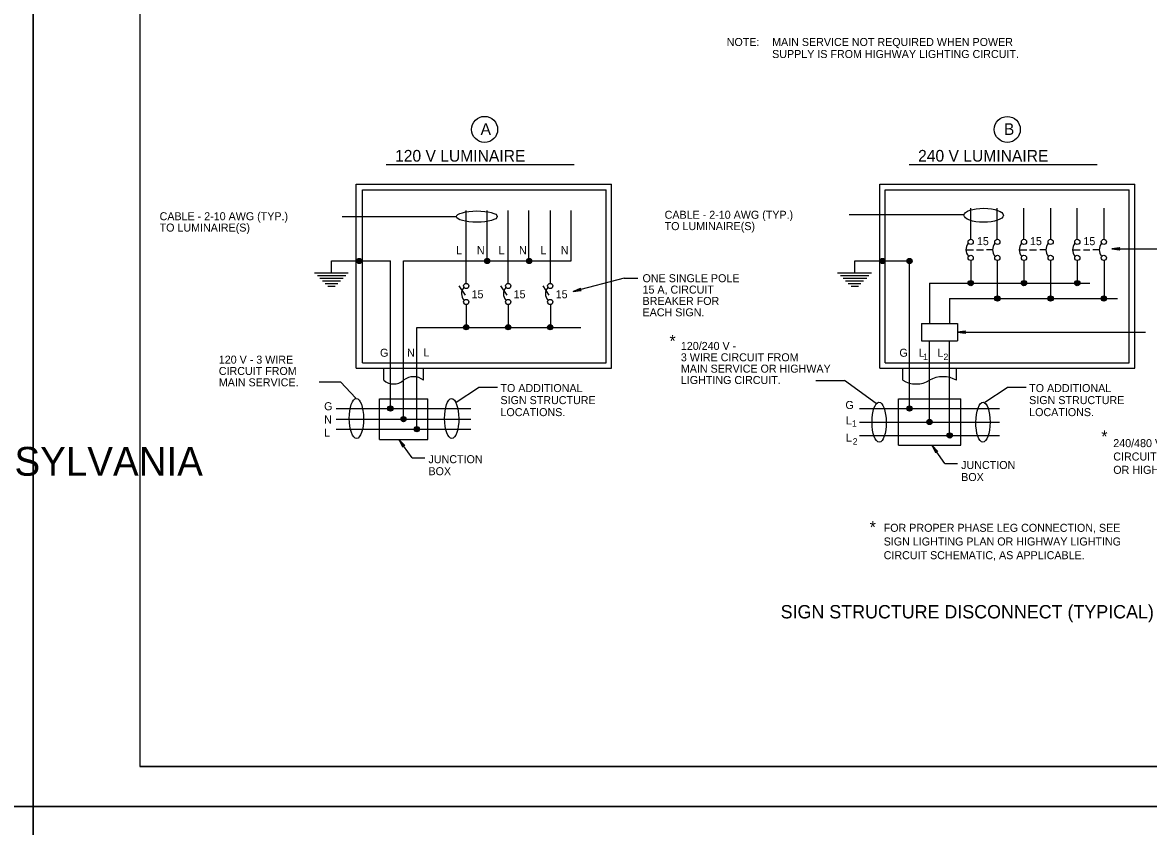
# Model space of a CAD drawing. Extents: x 36 to 2622, y -5330 to 219.
# Drawn here: x 872.9 to 1294.3, y -4743.3 to -4442.5 of the extents above; entities that cross this region are included whole.
import ezdxf

# ---------------------------------------------------------------- set-up
doc = ezdxf.new("R2010")
doc.units = 0
for name, color, linetype in [('1', 7, 'Continuous'), ('2', 7, 'Continuous'), ('3', 7, 'Continuous'), ('PLT-BNDY', 7, 'Continuous')]:
    doc.layers.add(name, color=color, linetype=linetype)

# ---------------------------------------------------------------- blocks, each defined once
blk = doc.blocks.new('RARROW')
at = {"layer": '3'}
blk.add_lwpolyline([(-2.2695, 0.285), (-2.184875, 0.12075), (0, 0), (-2.2695, 0.285), (-2.38575, 0.384625), (0, 0), (-2.183125, -0.108), (-2.262875, -0.2705), (0, 0), (-2.38575, -0.379125), (-2.262875, -0.2705)], dxfattribs=at)

msp = doc.modelspace()

# ---------------------------------------------------------------- linework, layer by layer
at = {"layer": '1'}
for p, q in [((916.86, -4156.83), (916.86, -4720.83)), ((1702.86, -4720.83), (916.86, -4720.83)), ((916.86, -4720.83), (1502.86, -4720.83))]:
    msp.add_line(p, q, dxfattribs=at)
at = {"layer": '2'}
for p, q in [((1008.98, -4495.7), (1079.36, -4495.7)), ((1204.73, -4495.7), (1275.11, -4495.7)), ((997.86, -4502.95), (1093.36, -4502.95)), ((997.86, -4571.83), (997.86, -4502.95)), ((1093.36, -4571.83), (1093.36, -4502.95)), ((1193.73, -4502.95), (1289.23, -4502.95)), ((1193.73, -4571.83), (1193.73, -4502.95)), ((1289.23, -4571.83), (1289.23, -4502.95)), ((1000.11, -4505.08), (1091.36, -4505.08)), ((1000.11, -4569.83), (1000.11, -4505.08)), ((1091.36, -4569.83), (1091.36, -4505.08)), ((1195.73, -4505.08), (1287.11, -4505.08)), ((1195.73, -4569.83), (1195.73, -4505.08)), ((1287.11, -4569.83), (1287.11, -4505.08)), ((1038.98, -4540.08), (1038.98, -4512.83)), ((1046.86, -4531.7), (1046.86, -4512.83)), ((1054.73, -4540.08), (1054.73, -4512.83)), ((1062.48, -4531.7), (1062.48, -4512.83)), ((1070.48, -4540.08), (1070.48, -4512.83)), ((1078.23, -4531.7), (1078.23, -4512.83)), ((1227.86, -4523.58), (1227.86, -4511.95)), ((1237.73, -4523.58), (1237.73, -4511.95)), ((1247.73, -4523.58), (1247.73, -4511.95)), ((1257.73, -4523.58), (1257.73, -4511.95)), ((1267.61, -4523.58), (1267.61, -4511.95)), ((1277.73, -4523.58), (1277.73, -4511.95)), ((1035.3, -4515.2), (992.51, -4515.2)), ((1182.36, -4514.33), (1225.36, -4514.33)), ((1225.98, -4527.58), (1228.86, -4527.58)), ((1229.98, -4527.58), (1232.61, -4527.58)), ((1235.98, -4527.58), (1233.73, -4527.58)), ((1245.98, -4527.58), (1248.86, -4527.58)), ((1249.86, -4527.58), (1252.48, -4527.58)), ((1255.86, -4527.58), (1253.61, -4527.58)), ((1265.86, -4527.58), (1268.73, -4527.58)), ((1269.98, -4527.58), (1272.36, -4527.58)), ((1275.98, -4527.58), (1273.48, -4527.58)), ((1280.61, -4527.2), (1299.36, -4527.2)), ((988.61, -4536.33), (988.61, -4531.7)), ((988.61, -4531.7), (1010.61, -4531.7)), ((1010.61, -4586.95), (1010.61, -4531.7)), ((1015.54, -4590.93), (1015.54, -4531.7)), ((1015.54, -4531.7), (1078.23, -4531.7)), ((1184.48, -4531.7), (1204.86, -4531.7)), ((1184.48, -4536.33), (1184.48, -4531.7)), ((1204.86, -4586.95), (1204.86, -4531.7)), ((1227.86, -4531.58), (1227.86, -4540.08)), ((1237.73, -4531.58), (1237.73, -4545.83)), ((1247.73, -4531.58), (1247.73, -4540.08)), ((1257.73, -4545.83), (1257.73, -4531.58)), ((1267.61, -4531.58), (1267.61, -4540.08)), ((1277.73, -4531.58), (1277.73, -4545.83)), ((994.86, -4536.33), (982.23, -4536.33)), ((993.98, -4537.33), (983.36, -4537.33)), ((992.98, -4538.33), (984.23, -4538.33)), ((1098.11, -4538.2), (1078.98, -4543.2)), ((1098.11, -4538.2), (1103.23, -4538.2)), ((1190.73, -4536.33), (1177.98, -4536.33)), ((1189.73, -4537.33), (1179.11, -4537.33)), ((1188.86, -4538.33), (1180.11, -4538.33)), ((991.98, -4539.33), (985.23, -4539.33)), ((990.98, -4540.33), (986.23, -4540.33)), ((989.98, -4541.33), (987.23, -4541.33)), ((1038.73, -4544.58), (1036.36, -4541.08)), ((1054.36, -4544.58), (1051.98, -4541.08)), ((1069.98, -4544.58), (1067.73, -4541.08)), ((1187.73, -4539.33), (1180.98, -4539.33)), ((1186.73, -4540.33), (1181.98, -4540.33)), ((1185.86, -4541.33), (1183.11, -4541.33)), ((1212.36, -4540.08), (1272.36, -4540.08)), ((1212.36, -4540.08), (1212.36, -4555.08)), ((1219.86, -4545.83), (1282.73, -4545.83)), ((1219.86, -4545.83), (1219.86, -4555.08)), ((1038.98, -4548.08), (1038.98, -4556.58)), ((1054.73, -4548.08), (1054.73, -4556.58)), ((1070.48, -4548.08), (1070.48, -4556.58)), ((1209.36, -4555.08), (1222.86, -4555.08)), ((1209.36, -4555.08), (1209.36, -4561.58)), ((1222.86, -4555.08), (1222.86, -4561.58)), ((1020.48, -4594.68), (1020.48, -4556.58)), ((1020.48, -4556.58), (1081.86, -4556.58)), ((1222.86, -4558.33), (1293.23, -4558.33)), ((1209.36, -4561.58), (1222.86, -4561.58)), ((1212.36, -4592.08), (1212.36, -4561.58)), ((1219.86, -4597.08), (1219.86, -4561.58)), ((997.86, -4571.83), (1093.36, -4571.83)), ((1000.11, -4569.83), (1091.36, -4569.83)), ((1008.11, -4576.33), (1008.11, -4571.83)), ((1022.98, -4576.33), (1022.98, -4571.83)), ((1193.73, -4571.83), (1289.23, -4571.83)), ((1195.73, -4569.83), (1287.11, -4569.83)), ((1202.36, -4576.33), (1202.36, -4571.83)), ((1222.48, -4576.33), (1222.48, -4571.83)), ((983.91, -4576.91), (991.91, -4576.91)), ((991.91, -4576.91), (997.73, -4583.12)), ((1035.18, -4584.58), (1043.53, -4579.12)), ((1050.68, -4579.12), (1043.53, -4579.12)), ((1169.82, -4576.48), (1180.59, -4576.48)), ((1192.39, -4585.13), (1180.59, -4576.48)), ((1233.05, -4584.58), (1241.41, -4579.12)), ((1248.55, -4579.12), (1241.41, -4579.12)), ((1006.48, -4598.53), (1006.48, -4583.33)), ((1006.48, -4583.33), (1024.61, -4583.33)), ((1024.61, -4598.53), (1024.61, -4583.33)), ((1200.73, -4583.33), (1224.11, -4583.33)), ((1200.73, -4600.7), (1200.73, -4583.33)), ((1224.11, -4600.7), (1224.11, -4583.33)), ((990.36, -4586.95), (1040.73, -4586.95)), ((1186.23, -4586.95), (1238.61, -4586.95)), ((990.36, -4590.93), (1040.73, -4590.93)), ((1186.23, -4592.08), (1238.61, -4592.08)), ((990.36, -4594.68), (1040.73, -4594.68)), ((1186.23, -4597.08), (1238.61, -4597.08)), ((1006.48, -4598.53), (1024.61, -4598.53)), ((1018.73, -4605.41), (1013.86, -4598.66)), ((1200.73, -4600.7), (1224.11, -4600.7)), ((1218.11, -4607.58), (1213.36, -4600.83)), ((1018.73, -4605.41), (1023.48, -4605.41)), ((1218.11, -4607.58), (1222.86, -4607.58))]:
    msp.add_line(p, q, dxfattribs=at)
for centre, radius in [((1045.87, -4482.52), 4.87), ((1241.49, -4482.54), 4.87), ((1227.8, -4524.6), 0.976), ((1237.77, -4524.59), 0.976), ((1247.74, -4524.6), 0.976), ((1257.71, -4524.59), 0.976), ((1267.69, -4524.6), 0.976), ((1277.65, -4524.59), 0.976), ((1227.8, -4530.59), 0.976), ((1237.77, -4530.59), 0.976), ((1247.74, -4530.59), 0.976), ((1257.71, -4530.59), 0.976), ((1267.69, -4530.59), 0.976), ((1277.65, -4530.59), 0.976), ((998.97, -4531.77), 0.976), ((998.97, -4531.77), 0.907), ((998.97, -4531.77), 0.838), ((998.97, -4531.77), 0.768), ((998.97, -4531.77), 0.699), ((998.97, -4531.77), 0.63), ((998.97, -4531.77), 0.56), ((998.97, -4531.77), 0.491), ((998.97, -4531.77), 0.422), ((998.97, -4531.77), 0.352), ((998.97, -4531.77), 0.283), ((998.97, -4531.77), 0.214), ((998.97, -4531.77), 0.144), ((998.97, -4531.77), 0.0749), ((1046.85, -4531.76), 0.976), ((1046.85, -4531.76), 0.907), ((1046.85, -4531.76), 0.838), ((1046.85, -4531.76), 0.768), ((1046.85, -4531.76), 0.699), ((1046.85, -4531.76), 0.63), ((1046.85, -4531.76), 0.56), ((1046.85, -4531.76), 0.491), ((1046.85, -4531.76), 0.422), ((1046.85, -4531.76), 0.352), ((1046.85, -4531.76), 0.283), ((1046.85, -4531.76), 0.214), ((1046.85, -4531.76), 0.144), ((1046.85, -4531.76), 0.0749), ((1062.56, -4531.76), 0.976), ((1062.56, -4531.76), 0.907), ((1062.56, -4531.76), 0.838), ((1062.56, -4531.76), 0.768), ((1062.56, -4531.76), 0.699), ((1062.56, -4531.76), 0.63), ((1062.56, -4531.76), 0.56), ((1062.56, -4531.76), 0.491), ((1062.56, -4531.76), 0.422), ((1062.56, -4531.76), 0.352), ((1062.56, -4531.76), 0.283), ((1062.56, -4531.76), 0.214), ((1062.56, -4531.76), 0.144), ((1062.56, -4531.76), 0.0749), ((1194.76, -4531.77), 0.976), ((1194.76, -4531.77), 0.907), ((1194.76, -4531.77), 0.838), ((1194.76, -4531.77), 0.768), ((1194.76, -4531.77), 0.699), ((1194.76, -4531.77), 0.63), ((1194.76, -4531.77), 0.56), ((1194.76, -4531.77), 0.491), ((1194.76, -4531.77), 0.422), ((1194.76, -4531.77), 0.352), ((1194.76, -4531.77), 0.283), ((1194.76, -4531.77), 0.214), ((1194.76, -4531.77), 0.144), ((1194.76, -4531.77), 0.0749), ((1204.87, -4531.76), 0.976), ((1204.87, -4531.76), 0.907), ((1204.87, -4531.76), 0.838), ((1204.87, -4531.76), 0.768), ((1204.87, -4531.76), 0.699), ((1204.87, -4531.76), 0.63), ((1204.87, -4531.76), 0.56), ((1204.87, -4531.76), 0.491), ((1204.87, -4531.76), 0.422), ((1204.87, -4531.76), 0.352), ((1204.87, -4531.76), 0.283), ((1204.87, -4531.76), 0.214), ((1204.87, -4531.76), 0.144), ((1204.87, -4531.76), 0.0749), ((1038.99, -4541.1), 0.976), ((1054.7, -4541.1), 0.976), ((1070.41, -4541.1), 0.976), ((1227.79, -4540.02), 0.976), ((1227.79, -4540.02), 0.907), ((1227.79, -4540.02), 0.838), ((1227.79, -4540.02), 0.768), ((1227.79, -4540.02), 0.699), ((1227.79, -4540.02), 0.63), ((1227.79, -4540.02), 0.56), ((1227.79, -4540.02), 0.491), ((1227.79, -4540.02), 0.422), ((1227.79, -4540.02), 0.352), ((1227.79, -4540.02), 0.283), ((1227.79, -4540.02), 0.214), ((1227.79, -4540.02), 0.144), ((1227.79, -4540.02), 0.0749), ((1247.74, -4540.02), 0.976), ((1247.74, -4540.02), 0.907), ((1247.74, -4540.02), 0.838), ((1247.74, -4540.02), 0.768), ((1247.74, -4540.02), 0.699), ((1247.74, -4540.02), 0.63), ((1247.74, -4540.02), 0.56), ((1247.74, -4540.02), 0.491), ((1247.74, -4540.02), 0.422), ((1247.74, -4540.02), 0.352), ((1247.74, -4540.02), 0.283), ((1247.74, -4540.02), 0.214), ((1247.74, -4540.02), 0.144), ((1247.74, -4540.02), 0.0749), ((1267.68, -4540.02), 0.976), ((1267.68, -4540.02), 0.907), ((1267.68, -4540.02), 0.838), ((1267.68, -4540.02), 0.768), ((1267.68, -4540.02), 0.699), ((1267.68, -4540.02), 0.63), ((1267.68, -4540.02), 0.56), ((1267.68, -4540.02), 0.491), ((1267.68, -4540.02), 0.422), ((1267.68, -4540.02), 0.352), ((1267.68, -4540.02), 0.283), ((1267.68, -4540.02), 0.214), ((1267.68, -4540.02), 0.144), ((1267.68, -4540.02), 0.0749), ((1038.99, -4547.09), 0.976), ((1054.7, -4547.09), 0.976), ((1070.41, -4547.09), 0.976), ((1237.77, -4545.79), 0.976), ((1237.77, -4545.79), 0.907), ((1237.77, -4545.79), 0.838), ((1237.77, -4545.79), 0.768), ((1237.77, -4545.79), 0.699), ((1237.77, -4545.79), 0.63), ((1237.77, -4545.79), 0.56), ((1237.77, -4545.79), 0.491), ((1237.77, -4545.79), 0.422), ((1237.77, -4545.79), 0.352), ((1237.77, -4545.79), 0.283), ((1237.77, -4545.79), 0.214), ((1237.77, -4545.79), 0.144), ((1237.77, -4545.79), 0.0749), ((1257.71, -4545.79), 0.976), ((1257.71, -4545.79), 0.907), ((1257.71, -4545.79), 0.838), ((1257.71, -4545.79), 0.768), ((1257.71, -4545.79), 0.699), ((1257.71, -4545.79), 0.63), ((1257.71, -4545.79), 0.56), ((1257.71, -4545.79), 0.491), ((1257.71, -4545.79), 0.422), ((1257.71, -4545.79), 0.352), ((1257.71, -4545.79), 0.283), ((1257.71, -4545.79), 0.214), ((1257.71, -4545.79), 0.144), ((1257.71, -4545.79), 0.0749), ((1277.65, -4545.79), 0.976), ((1277.65, -4545.79), 0.907), ((1277.65, -4545.79), 0.838), ((1277.65, -4545.79), 0.768), ((1277.65, -4545.79), 0.699), ((1277.65, -4545.79), 0.63), ((1277.65, -4545.79), 0.56), ((1277.65, -4545.79), 0.491), ((1277.65, -4545.79), 0.422), ((1277.65, -4545.79), 0.352), ((1277.65, -4545.79), 0.283), ((1277.65, -4545.79), 0.214), ((1277.65, -4545.79), 0.144), ((1277.65, -4545.79), 0.0749), ((1038.99, -4556.52), 0.976), ((1038.99, -4556.52), 0.907), ((1038.99, -4556.52), 0.838), ((1038.99, -4556.52), 0.768), ((1038.99, -4556.52), 0.699), ((1038.99, -4556.52), 0.63), ((1038.99, -4556.52), 0.56), ((1038.99, -4556.52), 0.491), ((1038.99, -4556.52), 0.422), ((1038.99, -4556.52), 0.352), ((1038.99, -4556.52), 0.283), ((1038.99, -4556.52), 0.214), ((1038.99, -4556.52), 0.144), ((1038.99, -4556.52), 0.0749), ((1054.7, -4556.52), 0.976), ((1054.7, -4556.52), 0.907), ((1054.7, -4556.52), 0.838), ((1054.7, -4556.52), 0.768), ((1054.7, -4556.52), 0.699), ((1054.7, -4556.52), 0.63), ((1054.7, -4556.52), 0.56), ((1054.7, -4556.52), 0.491), ((1054.7, -4556.52), 0.422), ((1054.7, -4556.52), 0.352), ((1054.7, -4556.52), 0.283), ((1054.7, -4556.52), 0.214), ((1054.7, -4556.52), 0.144), ((1054.7, -4556.52), 0.0749), ((1070.41, -4556.52), 0.976), ((1070.41, -4556.52), 0.907), ((1070.41, -4556.52), 0.838), ((1070.41, -4556.52), 0.768), ((1070.41, -4556.52), 0.699), ((1070.41, -4556.52), 0.63), ((1070.41, -4556.52), 0.56), ((1070.41, -4556.52), 0.491), ((1070.41, -4556.52), 0.422), ((1070.41, -4556.52), 0.352), ((1070.41, -4556.52), 0.283), ((1070.41, -4556.52), 0.214), ((1070.41, -4556.52), 0.144), ((1070.41, -4556.52), 0.0749), ((1010.6, -4586.94), 0.976), ((1010.6, -4586.94), 0.907), ((1010.6, -4586.94), 0.838), ((1010.6, -4586.94), 0.768), ((1010.6, -4586.94), 0.699), ((1010.6, -4586.94), 0.63), ((1010.6, -4586.94), 0.56), ((1010.6, -4586.94), 0.491), ((1010.6, -4586.94), 0.422), ((1010.6, -4586.94), 0.352), ((1010.6, -4586.94), 0.283), ((1010.6, -4586.94), 0.214), ((1010.6, -4586.94), 0.144), ((1010.6, -4586.94), 0.0749), ((1204.87, -4586.94), 0.976), ((1204.87, -4586.94), 0.907), ((1204.87, -4586.94), 0.838), ((1204.87, -4586.94), 0.768), ((1204.87, -4586.94), 0.699), ((1204.87, -4586.94), 0.63), ((1204.87, -4586.94), 0.56), ((1204.87, -4586.94), 0.491), ((1204.87, -4586.94), 0.422), ((1204.87, -4586.94), 0.352), ((1204.87, -4586.94), 0.283), ((1204.87, -4586.94), 0.214), ((1204.87, -4586.94), 0.144), ((1204.87, -4586.94), 0.0749), ((1015.54, -4590.93), 0.976), ((1015.54, -4590.93), 0.907), ((1015.54, -4590.93), 0.838), ((1015.54, -4590.93), 0.768), ((1015.54, -4590.93), 0.699), ((1015.54, -4590.93), 0.63), ((1015.54, -4590.93), 0.56), ((1015.54, -4590.93), 0.491), ((1015.54, -4590.93), 0.422), ((1015.54, -4590.93), 0.352), ((1015.54, -4590.93), 0.283), ((1015.54, -4590.93), 0.214), ((1015.54, -4590.93), 0.144), ((1015.54, -4590.93), 0.0749), ((1212.4, -4591.99), 0.976), ((1212.4, -4591.99), 0.907), ((1212.4, -4591.99), 0.838), ((1212.4, -4591.99), 0.768), ((1212.4, -4591.99), 0.699), ((1212.4, -4591.99), 0.63), ((1212.4, -4591.99), 0.56), ((1212.4, -4591.99), 0.491), ((1212.4, -4591.99), 0.422), ((1212.4, -4591.99), 0.352), ((1212.4, -4591.99), 0.283), ((1212.4, -4591.99), 0.214), ((1212.4, -4591.99), 0.144), ((1212.4, -4591.99), 0.0749), ((1020.48, -4594.68), 0.976), ((1020.48, -4594.68), 0.907), ((1020.48, -4594.68), 0.838), ((1020.48, -4594.68), 0.768), ((1020.48, -4594.68), 0.699), ((1020.48, -4594.68), 0.63), ((1020.48, -4594.68), 0.56), ((1020.48, -4594.68), 0.491), ((1020.48, -4594.68), 0.422), ((1020.48, -4594.68), 0.352), ((1020.48, -4594.68), 0.283), ((1020.48, -4594.68), 0.214), ((1020.48, -4594.68), 0.144), ((1020.48, -4594.68), 0.0749), ((1219.93, -4597.03), 0.976), ((1219.93, -4597.03), 0.907), ((1219.93, -4597.03), 0.838), ((1219.93, -4597.03), 0.768), ((1219.93, -4597.03), 0.699), ((1219.93, -4597.03), 0.63), ((1219.93, -4597.03), 0.56), ((1219.93, -4597.03), 0.491), ((1219.93, -4597.03), 0.422), ((1219.93, -4597.03), 0.352), ((1219.93, -4597.03), 0.283), ((1219.93, -4597.03), 0.214), ((1219.93, -4597.03), 0.144), ((1219.93, -4597.03), 0.0749)]:
    msp.add_circle(centre, radius, dxfattribs=at)
for centre, radius, start, end in [((1229.76, -4527.53), 3.73, 139.9422, 220.6112), ((1239.73, -4527.53), 3.73, 139.9422, 220.6112), ((1249.71, -4527.53), 3.73, 139.9422, 220.6112), ((1259.67, -4527.53), 3.73, 139.9422, 220.6112), ((1269.65, -4527.53), 3.73, 139.9422, 220.6112), ((1279.62, -4527.53), 3.73, 139.9422, 220.6112), ((1040.96, -4544.03), 3.73, 139.9422, 220.6112), ((1056.67, -4544.03), 3.73, 139.9422, 220.6112), ((1072.38, -4544.03), 3.73, 139.9422, 220.6112), ((1011.83, -4571.92), 5.82, 230.1911, 309.8089), ((1019.28, -4580.87), 5.82, 50.1911, 129.8089)]:
    msp.add_arc(centre, radius, start, end, dxfattribs=at)
for centre, major_axis, ratio in [((1042.97, -4515.14), (7.66, 0.04), 0.274299), ((1232.65, -4514.64), (-7.37, 0.05), 0.356583), ((997.9, -4590.67), (0.05, -7.47), 0.356583), ((1033.55, -4590.7), (-0.05, 7.47), 0.356583), ((1193.52, -4592.08), (-0.05, 7.47), 0.356583), ((1232.39, -4592.08), (0.05, 7.47), 0.356583)]:
    msp.add_ellipse(centre, major_axis=major_axis, ratio=ratio, dxfattribs=at)
for centre, major_axis in [((1207.39, -4571.92), (7.83, 0)), ((1217.42, -4580.87), (-7.83, 0))]:
    msp.add_ellipse(centre, major_axis=major_axis, ratio=0.74367, start_param=4.017593, end_param=5.407185, dxfattribs=at)
at = {"layer": 'PLT-BNDY'}
for points in [[(35.86, -4141.83), (876.86, -4141.83), (876.86, -4735.83), (35.86, -4735.83)], [(876.86, -4141.83), (1717.86, -4141.83), (1717.86, -4735.83), (876.86, -4735.83)], [(35.86, -4735.83), (876.86, -4735.83), (876.86, -5329.83), (35.86, -5329.83)], [(876.86, -4735.83), (1717.86, -4735.83), (1717.86, -5329.83), (876.86, -5329.83)]]:
    msp.add_lwpolyline(points, close=True, dxfattribs=at)

# ---------------------------------------------------------------- block references
at = {"layer": '2', "xscale": 1.2574347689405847}
for p, yscale, rotation in [((1280.61, -4527.2), 1.3092961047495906, 180), ((1078.98, -4543.2), 1.3092961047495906, -165.02963275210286), ((1222.86, -4558.33), 1.3092961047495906, 180), ((1013.86, -4598.66), 1.3092961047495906, 125.77877272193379), ((1213.36, -4600.83), 1.3092961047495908, 125.50173697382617)]:
    msp.add_blockref('RARROW', p, dxfattribs=dict(at, yscale=yscale, rotation=rotation))

# ---------------------------------------------------------------- texts
at = {"layer": '1'}
msp.add_text('COMMONWEALTH OF PENNSYLVANIA', height=10.7828, dxfattribs=at).set_placement((674.45, -4612.1))
at = {"layer": '2'}
for s, height, p in [('NOTE:', 2.996, (1136.48, -4451.31)), ('MAIN SERVICE NOT REQUIRED WHEN POWER', 2.9955, (1153.48, -4451.31)), ('SUPPLY IS FROM HIGHWAY LIGHTING CIRCUIT.', 2.9955, (1153.48, -4455.81)), ('A', 4.37, (1044.36, -4484.58)), ('B', 4.37, (1240.23, -4484.58)), ('120 V LUMINAIRE', 4.3747, (1012.36, -4494.58)), ('240 V LUMINAIRE', 4.3747, (1208.11, -4494.58)), ('CABLE - 2-10 AWG (TYP.)', 2.9955, (1113.25, -4515.95)), ('CABLE - 2-10 AWG (TYP.)', 2.9955, (924.23, -4516.51)), ('TO LUMINAIRE(S)', 2.9955, (1113.25, -4520.2)), ('TO LUMINAIRE(S)', 2.9955, (924.23, -4520.75)), ('15', 2.996, (1230.11, -4525.83)), ('15', 2.996, (1249.98, -4525.83)), ('15', 2.996, (1269.98, -4525.83)), ('L', 3, (1035.23, -4529.2)), ('N', 3, (1042.98, -4529.2)), ('L', 3, (1051.11, -4529.2)), ('N', 3, (1058.73, -4529.2)), ('L', 3, (1066.73, -4529.2)), ('N', 3, (1074.36, -4529.2)), ('ONE SINGLE POLE', 2.9955, (1104.98, -4539.7)), ('15', 2.996, (1040.98, -4545.7)), ('15', 2.996, (1056.73, -4545.7)), ('15', 2.996, (1072.48, -4545.7)), ('15 A, CIRCUIT', 2.9955, (1104.98, -4543.95)), ('BREAKER FOR', 2.9955, (1104.98, -4548.2)), ('EACH SIGN.', 2.996, (1104.98, -4552.45)), ('*', 4.49, (1115.07, -4563.9)), ('120/240 V -', 2.9955, (1119.32, -4565.03)), ('120 V - 3 WIRE', 2.9955, (946.39, -4570.16)), ('G', 3, (1006.73, -4567.58)), ('L', 3, (1022.98, -4567.45)), ('3 WIRE CIRCUIT FROM', 2.9955, (1119.32, -4569.28)), ('G', 3, (1201.11, -4567.58)), ('L', 3, (1208.36, -4567.58)), ('1', 2.43, (1209.98, -4568.83)), ('L', 3, (1215.36, -4567.58)), ('2', 2.43, (1217.61, -4568.83)), ('CIRCUIT FROM', 2.9955, (946.39, -4574.4)), ('MAIN SERVICE OR HIGHWAY', 2.9955, (1119.32, -4573.53)), ('MAIN SERVICE.', 2.9955, (946.39, -4578.65)), ('LIGHTING CIRCUIT.', 2.9955, (1119.32, -4577.78)), ('TO ADDITIONAL', 2.9955, (1051.81, -4580.8)), ('TO ADDITIONAL', 2.9955, (1249.68, -4580.8)), ('G', 3, (985.81, -4587.6)), ('SIGN STRUCTURE', 2.9955, (1051.81, -4585.3)), ('G', 3, (1180.91, -4587.13)), ('SIGN STRUCTURE', 2.9955, (1249.68, -4585.3)), ('LOCATIONS.', 2.996, (1051.81, -4589.8)), ('LOCATIONS.', 2.996, (1249.68, -4589.8)), ('N', 3, (985.81, -4592.56)), ('L', 3, (1181.1, -4592.91)), ('1', 2.43, (1183.37, -4593.79)), ('L', 3, (985.81, -4597.5)), ('L', 3, (1181.1, -4599.35)), ('*', 4.49, (1276.66, -4599.66)), ('2', 2.43, (1183.65, -4600.49)), ('240/480 V - 4 WIRE', 2.9955, (1281.16, -4601.4)), ('JUNCTION', 2.996, (1024.86, -4607.41)), ('CIRCUIT FROM MAIN SERVICE', 2.9955, (1281.16, -4606.4)), ('BOX', 2.996, (1024.86, -4611.91)), ('JUNCTION', 2.996, (1224.23, -4609.58)), ('OR HIGHWAY LIGHTING CIRCUIT.', 2.9955, (1281.16, -4611.39)), ('BOX', 2.996, (1224.23, -4614.08)), ('*', 4.49, (1189.98, -4633.58)), ('FOR PROPER PHASE LEG CONNECTION, SEE', 2.9955, (1195.23, -4633.08)), ('SIGN LIGHTING PLAN OR HIGHWAY LIGHTING', 2.9955, (1195.23, -4638.2)), ('CIRCUIT SCHEMATIC, AS APPLICABLE.', 2.9955, (1195.23, -4643.33)), ('SIGN STRUCTURE DISCONNECT (TYPICAL)', 5, (1156.67, -4665.49))]:
    msp.add_text(s, height=height, dxfattribs=at).set_placement(p)
msp.add_text('N', height=3, rotation=360, dxfattribs=at).set_placement((1016.85, -4567.53))

doc.saveas('drawing.dxf')
